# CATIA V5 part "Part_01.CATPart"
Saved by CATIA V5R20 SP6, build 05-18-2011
Part number: Part_01
Bounding box of the stored display mesh (mm): x -7.5 to 7.5, y 0 to 18, z 0 to 39
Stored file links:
  E:\#01 CATIA Lecture Materials\#16 3D Print Test\3D Print Test\14th Test\Part_01.CATPart
  E:\#01 CATIA Lecture Materials\#16 3D Print Test\3D Print Test\14th Test\Part_02.CATPart
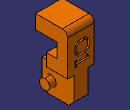
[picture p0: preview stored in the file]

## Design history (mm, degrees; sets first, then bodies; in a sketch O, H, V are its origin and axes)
Set1 "Reference Data"
  Point1 "Center Point": (0, 0, 0)
Body1 (main body)
  Sketch1 on yz-plane, origin (0, 0, 0), H (0, 0, -1), V (0, 1, 0)
    line L1 (0, 0) -> (0, 18)
    line L2 (0, 18) -> (-39, 18)
    line L3 (-39, 18) -> (-39, 0)
    point P3 (-39, 0)
    line L4 (-39, 0) -> (-31, 0)
    line L5 (-31, 0) -> (-31, 12)
    line L6 (-31, 12) -> (-23, 12)
    line L7 (-23, 12) -> (-23, 6)
    line L8 (-23, 6) -> (-16, 6)
    line L9 (-16, 6) -> (-16, 0)
    line L10 (-16, 0) -> (0, 0)
    distance L10 L2 = 18
    distance L1 L3 = 39
    distance L1 L7 = 23
    distance L7 L5 = 8
    distance L4 L8 = 6
    distance L4 L6 = 12
    distance L9 V = 16
    vertical: L1 V, L3 V, L5 V, L7 V, L9 V
    horizontal: L2 H, L4 H, L6 H, L8 H, L10 H
    coincidence: P3 H
  Sketch2 on zx-plane, origin (0, 0, 0), H (0, 0, -1), V (-1, 0, 0)
    line L1 (-39, -7.5) -> (-16, -7.5)
    line L2 (-16, -7.5) -> (-16, -3.9)
    line L3 (-16, -3.9) -> (0, -3.9)
    point P4 (0, -3.9)
    line L4 (0, -3.9) -> (0, 3.9)
    line L5 (0, 3.9) -> (-16, 3.9)
    point P6 (-16, 3.9)
    line L6 (-16, 3.9) -> (-16, 7.5)
    line L7 (-16, 7.5) -> (-39, 7.5)
    line L8 (-39, 7.5) -> (-39, -7.5)
    reference projected point E1 (-16, 0) from Sketch1.L9
    reference projected point E2 (-39, 0) from Sketch1.L3
    distance L7 L1 = 15
    distance L5 L3 = 7.8
    horizontal: L1 H, L3 H, L5 H, L7 H
    vertical: L2 V, L4 V, L6 V, L8 V
    coincidence: P4 V, P6 L2, L6 E1, L8 E2
    symmetry: L7 L1 H, L5 L3 H
  SolidCombine1: FirstComponentDirection Sketch1, FirstComponentProfile Sketch1, SecondComponentDirection Sketch2, SecondComponentProfile Sketch2
  Fillet1: radius 3, on edge [face of SolidCombine1 from Sketch2.L8 | face of SolidCombine1 from Sketch1.L2]
  Sketch3 on yz-plane, origin (0, 0, 0), H (0, 0, -1), V (0, 1, 0)
    circle A1 centre (-7, 5) radius 2.9
    point P1 (-7, 5)
    reference projected line E1 (0, 18) -> (-16, 18) from edge [face of SolidCombine1 from Sketch1.L2 | face of SolidCombine1 from Sketch2.L3]
    radius A1 = 2.9
    distance V P1 = 7
    distance E1 P1 = 13
  Pad1: profile Sketch3, direction (1, 0, 0), length 7.5, mirrored extent
  Chamfer1: length 3, angle 45, on edge [face of SolidCombine1 from Sketch1.L2 | face of SolidCombine1 from Sketch2.L4]; edge [face of SolidCombine1 from Sketch2.L4 | face of SolidCombine1 from Sketch1.L10]
  Sketch4 on face of SolidCombine1 from Sketch1.L2, origin (0, 18, 0), H (0, 0, -1), V (-1, 0, 0)
    polyline C1
    polyline C2
    polyline C3
    polyline C4
    point P1 (-21.1029, 4.1481)
    point P6 (-21.1029, 4.1481)
    coincidence: P1 P6
  Pocket1: profile Sketch4, direction (0, -1, 0), length 1, thin wall 1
